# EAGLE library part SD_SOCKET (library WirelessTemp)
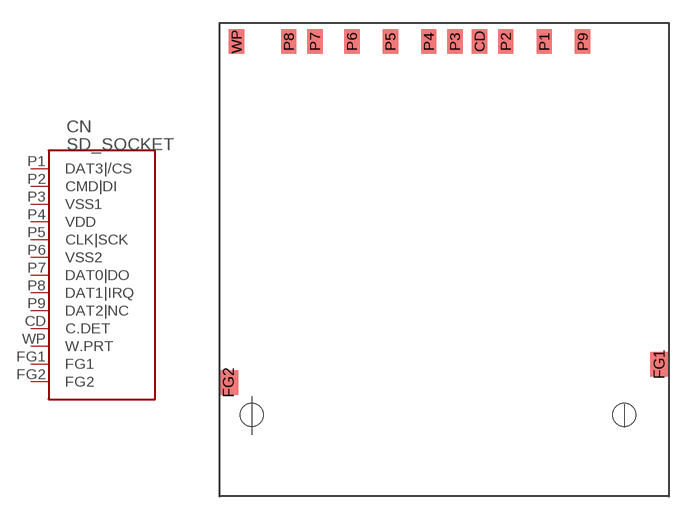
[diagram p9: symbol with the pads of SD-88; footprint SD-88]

Designator prefix CN

## SD_SOCKET  [SD-88]
CD  C.DET  out
FG1  FG1  pwr
FG2  FG2  pwr
P1  DAT3|/CS  in
P2  CMD|DI  in
P3  VSS1  pwr
P4  VDD  pwr
P5  CLK|SCK  in
P6  VSS2  pwr
P7  DAT0|DO  out
P8  DAT1|IRQ  nc
P9  DAT2|NC  nc
WP  W.PRT  out

## Footprint SD-88 (pad centres in mm)
smd 1 x 1.6: CD 15.8,0; P1 20,0; P2 17.5,0; P3 14.2,0; P4 12.5,0; P5 10,0; P6 7.5,0; P7 5.1,0; P8 3.4,0; P9 22.5,0; WP 0,0
smd 1.2 x 1.6: FG1 27.5,-21; FG2 -0.5,-22.2
hole 1.5 at 1,-24.3
hole 1.5 at 25.2,-24.3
